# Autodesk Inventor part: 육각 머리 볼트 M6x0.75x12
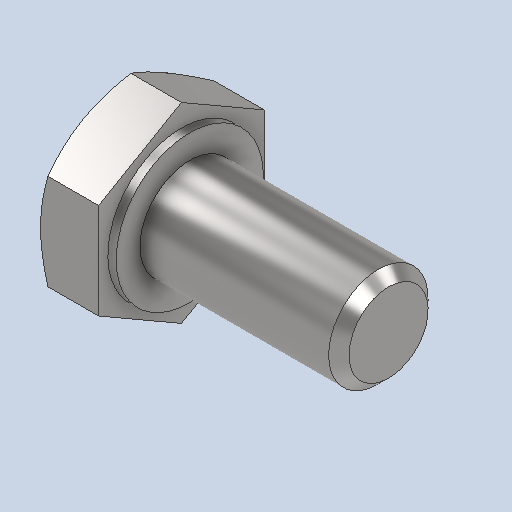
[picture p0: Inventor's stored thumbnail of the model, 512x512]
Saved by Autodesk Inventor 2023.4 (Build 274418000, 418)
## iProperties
Created: 2024-09
Part Number: 육각 머리 볼트 M6x0.75x12
Material: 강철, 연강
Description: 6각 머리 볼트 및 6각 머리 나사
Document SubType Name: Modeling
Designer: 11
Density: 7.85 g/cm^3
Appearance: 기본값
Author: jhkim
Sending System: Autodesk Inventor 2025
Preprocessor: ST-DEVELOPER v20
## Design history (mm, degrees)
node "육각 머리 볼트 M6x0.75x121"
node "솔리드1"
body "Solid1"
